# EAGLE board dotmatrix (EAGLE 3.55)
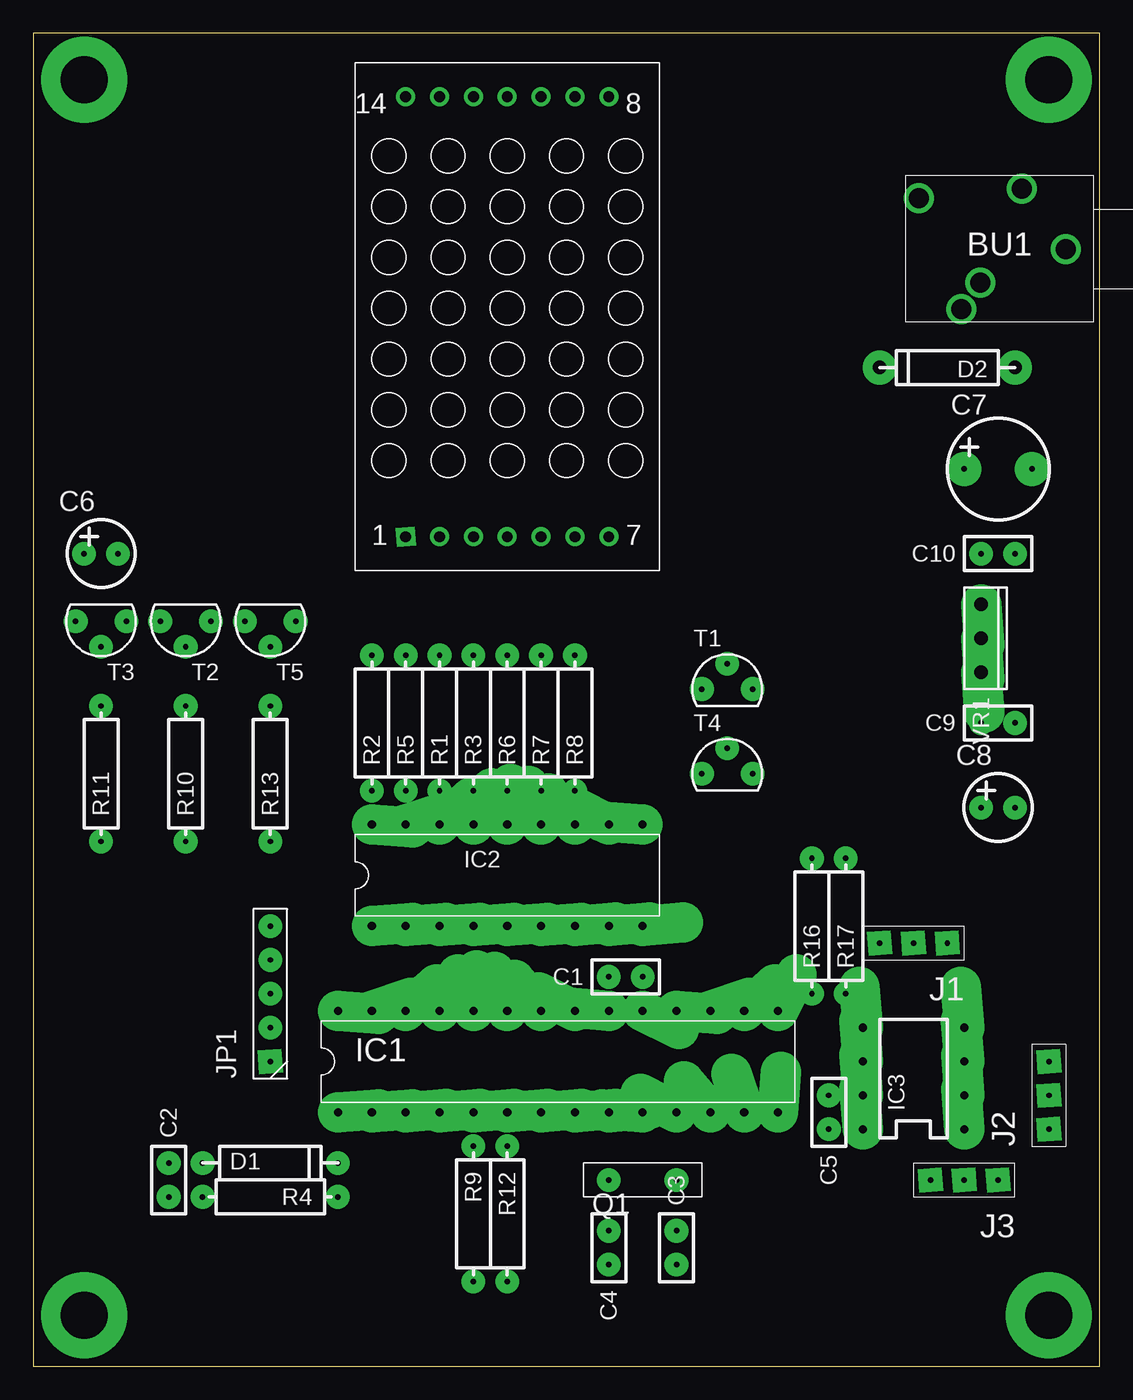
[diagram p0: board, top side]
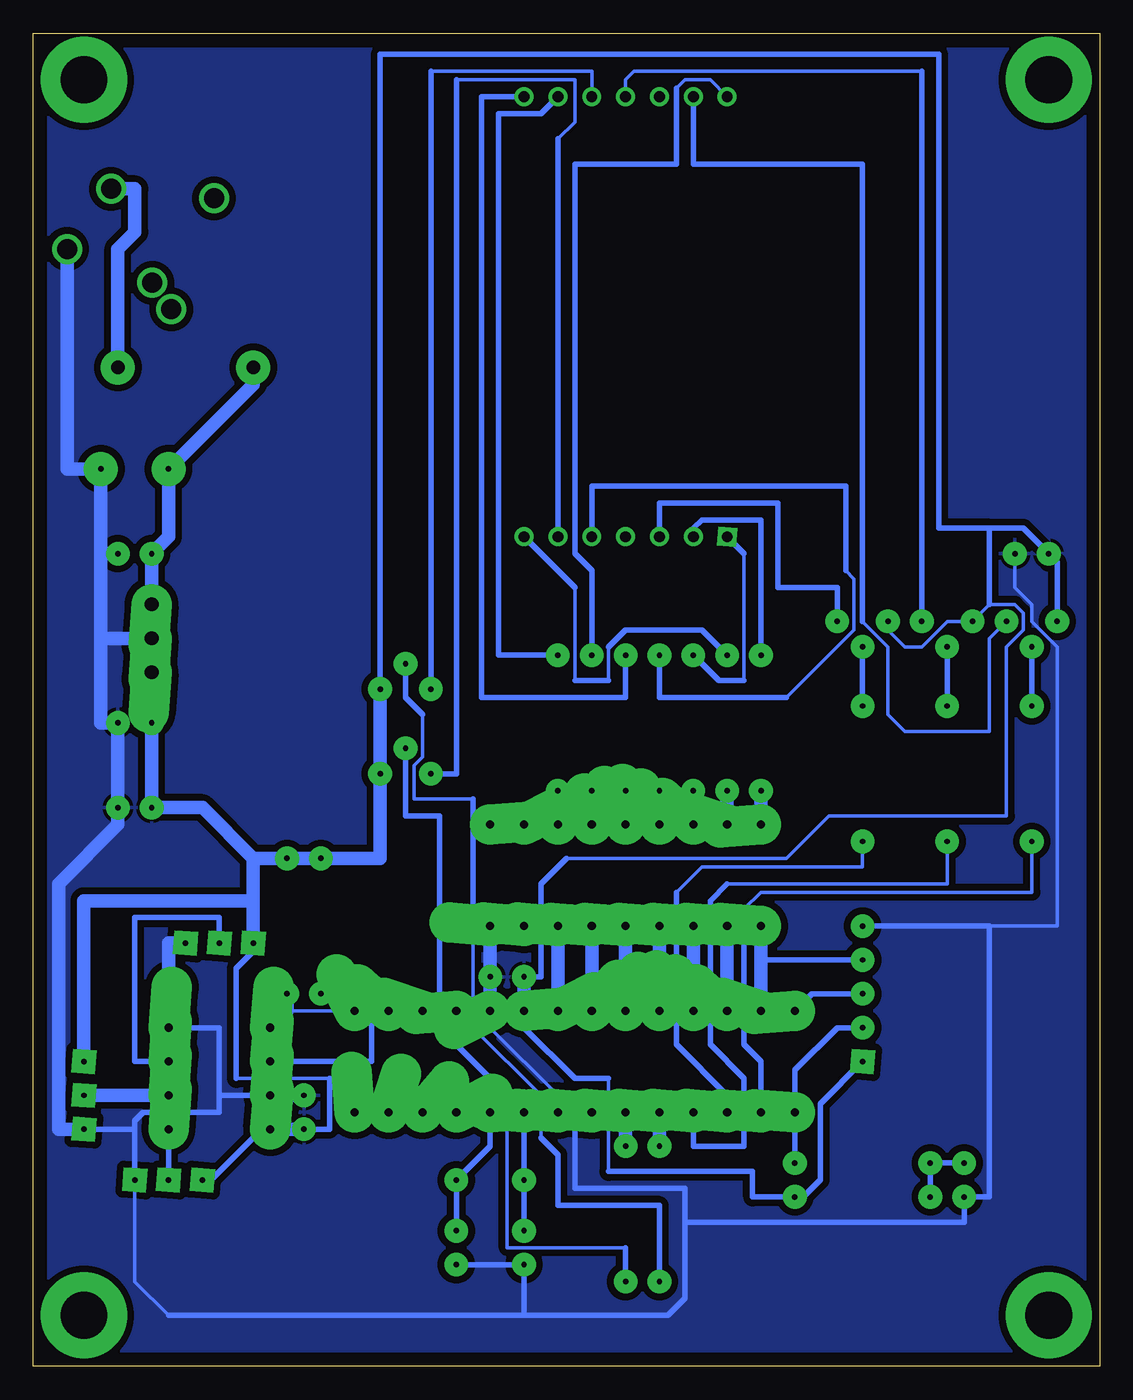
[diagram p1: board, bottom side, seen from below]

Size 80 x 100 mm. Coordinates in mm from the lower left corner, seen from the top.
Outline: 0,0 80,0 80,100 0,100 0,0
Copper layers used: Bottom

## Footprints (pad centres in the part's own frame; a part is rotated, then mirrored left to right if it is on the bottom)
_3,5MM = drill 1.499 pad 2.184 round:  0,0;  3.302,-4.521;  7.823,4.521;  6.401,2.54;  11.024,-3.81
RM2,5 = drill 0.406 pad 1.778 round:  -1.27,0;  1.27,0
KO01 = drill 0.406 pad 1.778 round:  -1.27,0;  1.27,0
KO02 = drill 0.406 pad 2.54 round:  -2.54,0;  2.54,0
O04 = drill 0.406 pad 1.778 round:  -5.08,0;  5.08,0
O_1A = drill 1.016 pad 2.54 round:  -5.08,0;  5.08,0
TA1211 = drill 0.813 pad 1.422 square:  0,0 | drill 0.813 pad 1.422 round:  2.54,0;  5.08,0;  7.62,0;  10.16,0;  12.7,0;  15.24,0;  15.24,33.02;  12.7,33.02;  10.16,33.02;  7.62,33.02;  5.08,33.02;  2.54,33.02;  0,33.02
L-28SB = drill 0.61 pad 3.048 offset:  -16.51,-3.81;  -13.97,-3.81;  -1.27,-3.81;  1.27,-3.81;  -11.43,-3.81;  -8.89,-3.81;  -3.81,-3.81;  -6.35,-3.81;  3.81,-3.81;  6.35,-3.81;  8.89,-3.81;  11.43,-3.81;  13.97,-3.81;  16.51,-3.81;  16.51,3.81;  13.97,3.81;  11.43,3.81;  8.89,3.81;  6.35,3.81;  3.81,3.81;  1.27,3.81;  -1.27,3.81;  -3.81,3.81;  -6.35,3.81;  -8.89,3.81;  -11.43,3.81;  -13.97,3.81;  -16.51,3.81
L-18B = drill 0.61 pad 3.048 offset:  -10.16,-3.81;  -7.62,-3.81;  5.08,-3.81;  7.62,-3.81;  -5.08,-3.81;  -2.54,-3.81;  2.54,-3.81;  0,-3.81;  10.16,-3.81;  10.16,3.81;  7.62,3.81;  5.08,3.81;  2.54,3.81;  0,3.81;  -2.54,3.81;  -5.08,3.81;  -7.62,3.81;  -10.16,3.81
L-8B = drill 0.61 pad 3.048 offset:  -3.81,-3.81;  -1.27,-3.81;  1.27,-3.81;  3.81,-3.81;  3.81,3.81;  1.27,3.81;  -1.27,3.81;  -3.81,3.81
MPER_3 = drill 0.406 pad 1.778 square:  -2.54,0;  0,0;  2.54,0
5 = drill 0.406 pad 1.778 square:  0,0 | drill 0.406 pad 1.778 round:  5.08,0;  10.16,0;  7.62,0;  2.54,0
ARZ_ST = drill 0.406 pad 1.778 round:  -2.54,0;  2.54,0
S04 = drill 0.406 pad 1.778 round:  -5.08,0;  5.08,0
92 = drill 0.406 pad 1.778 round:  -1.905,0;  0,1.905;  1.905,0
HRUNG = drill 3.505 pad 6.452 round:  0,0
220A = drill 1.016 pad 3.048 offset:  -2.54,0;  0,0;  2.54,0

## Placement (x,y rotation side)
BU1  BU_3,5MM  [_3,5MM]  77.47,83.82 180 top
C1  C100NK  [RM2,5]  44.45,29.21 180 top
C2  C100NK  [RM2,5]  10.16,13.97 90 top
C3  22p  [RM2,5]  48.26,8.89 90 top
C4  22p  [RM2,5]  43.18,8.89 270 top
C5  C100NK  [RM2,5]  59.69,19.05 270 top
C6  100u  [KO01]  5.08,60.96 0 top
C7  470u /25V  [KO02]  72.39,67.31 0 top
C8  100u  [KO01]  72.39,41.91 0 top
C9  C100NK  [RM2,5]  72.39,48.26 180 top
C10  C100NK  [RM2,5]  72.39,60.96 180 top
D1  BAT41  [O04]  17.78,15.24 0 top
D2  1N4001  [O_1A]  68.58,74.93 180 top
DIS1  DOTA1211  [TA1211]  27.94,62.23 0 top
IC1  16F873P  [L-28SB]  39.37,22.86 0 top
IC2  ULN2803A  [L-18B]  35.56,36.83 0 top
IC3  24C16  [L-8B]  66.04,21.59 90 top
J1  JUMPER_3  [MPER_3]  66.04,31.75 180 top
J2  JUMPER_3  [MPER_3]  76.2,20.32 90 top
J3  JUMPER_3  [MPER_3]  69.85,13.97 180 top
JP1  PINHD-1X5  [5]  17.78,22.86 90 top
Q1  4MHz  [ARZ_ST]  45.72,13.97 0 top
R1  100  [S04]  30.48,48.26 90 top
R2  100  [S04]  25.4,48.26 90 top
R3  100  [S04]  33.02,48.26 90 top
R4  47k  [S04]  17.78,12.7 180 top
R5  100  [S04]  27.94,48.26 90 top
R6  100  [S04]  35.56,48.26 90 top
R7  100  [S04]  38.1,48.26 90 top
R8  100  [S04]  40.64,48.26 90 top
R9  1k  [S04]  33.02,11.43 270 top
R10  1k  [S04]  11.43,44.45 90 top
R11  1k  [S04]  5.08,44.45 90 top
R12  1k  [S04]  35.56,11.43 270 top
R13  1k  [S04]  17.78,44.45 90 top
R16  3k3  [S04]  58.42,33.02 90 top
R17  3k3  [S04]  60.96,33.02 90 top
T1  BC327  [92]  52.07,50.8 0 top
T2  BC327  [92]  11.43,55.88 180 top
T3  BC327  [92]  5.08,55.88 180 top
T4  BC327  [92]  52.07,44.45 0 top
T5  BC327  [92]  17.78,55.88 180 top
U$15  BOHRUNG  [HRUNG]  76.2,96.52 0 top
U$16  BOHRUNG  [HRUNG]  76.2,3.81 0 top
U$26  BOHRUNG  [HRUNG]  3.81,3.81 0 top
U$27  BOHRUNG  [HRUNG]  3.81,96.52 0 top
VR1  7805  [220A]  71.12,54.61 270 top

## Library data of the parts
BU1 = bts
C1-C10 D1 D2 IC1-IC3 J1-J3 JP1 Q1 R1-R13 R16 R17 T1-T5 VR1 = holg_plt
DIS1 = ic_holg
U$15 U$16 U$26 U$27 = holgnorm

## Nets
+5V: C1. C5. C6. C8. C9. IC1. IC3. J1. J2. J3. JP1. R4. R16. R17. T1. T2. T3. T4. T5. VR1.
GND: BU1. C1. C2. C3. C4. C5. C6. C7. C8. C9. C10. IC1. IC2. IC3. J1. J2. J3. JP1. VR1.
N$1: IC1. R10.
N$2: DIS1. R1.
N$3: IC3. J1.
N$4: IC2. R1.
N$5: IC3. J2.
N$6: DIS1. R2.
N$7: IC2. R2.
N$8: DIS1. R3.
N$9: IC2. R3.
N$10: DIS1. R5.
N$11: IC2. R5.
N$12: DIS1. R6.
N$13: IC2. R6.
N$14: IC2. R7.
N$15: IC2. R8.
N$16: DIS1. R7.
N$17: DIS1. R8.
N$18: IC1. IC2. JP1.
N$19: IC1. IC2.
N$20: IC1. IC2.
N$21: IC1. IC2.
N$22: IC1. IC2.
N$23: IC1. IC2.
N$24: IC1. IC2.
N$25: IC3. J3.
N$26: DIS1. T1.
N$27: DIS1. T2.
N$28: DIS1. T3.
N$29: R9. T1.
N$30: R10. T2.
N$31: R11. T3.
N$32: R12. T4.
N$33: R13. T5.
N$34: IC1. R9.
N$35: D1. IC1. JP1.
N$36: IC1. R11.
N$37: DIS1. T4.
N$38: DIS1. T5.
N$39: IC1. R12.
N$40: IC1. R13.
N$41: C2. D1. R4.
N$42: BU1. D2.
N$43: C7. C10. D2. VR1.
N$44: C3. IC1. Q1.
N$46: C4. IC1. Q1.
N$47: IC1. IC3. R17.
N$49: IC1. JP1.
N$50: IC1. IC3. R16.

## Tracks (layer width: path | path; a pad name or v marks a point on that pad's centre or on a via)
+5V
  Bottom 0.254: 64.77,21.59 57.78,21.59 | 3.81,60.33 3.17,60.33 | T5. 15.88,55.24 14.61,53.98 13.34,53.98 11.43,55.88 T2. 8.26,57.15 6.35,57.15 5.71,56.52 5.71,55.24 6.99,53.98 6.99,41.27 20.32,41.27 23.5,38.1 40.01,38.1 | 22.23,12.7 22.86,12.7 | 36.83,14.61 36.83,21.59
  Bottom 0.406: C5. 57.78,17.78 57.78,21.59 | 64.77,21.59 64.77,29.84 63.5,31.11 J1. | 3.17,60.33 T3. | 3.81,60.33 3.81,60.96 5.71,62.87 8.26,62.87 | 8.26,57.15 8.26,62.87 | 22.23,12.7 20.95,13.97 20.95,19.68 17.78,22.86 | 36.83,21.59 39.37,21.59 43.18,25.4 43.18,26.67 | 36.83,14.61 26.04,14.61 26.04,12.7 22.86,12.7 | 40.01,38.1 41.91,36.2 41.91,29.21 C1. | 8.26,62.87 12.06,62.87 12.06,98.42 53.98,98.42 T1. | IC3. 62.87,17.78 66.67,13.97 J3.
  Bottom 1.016: C5. IC3. | T1. T4. 53.98,38.1 R16. R17. 63.5,38.1 | 63.5,38.1 63.5,34.92 | 63.5,34.92 J1. | 63.5,34.92 76.2,34.92 J2. | 43.18,26.67 C1. | VR1. C9. 71.12,41.91 67.31,41.91 63.5,38.1
GND
  Bottom 0.254: 8.26,33.02 3.17,33.02 3.17,53.98 5.08,55.88 5.08,57.15 6.35,58.42 C6. | 45.72,26.67 45.72,25.4 40.64,20.32 40.64,19.05 | 69.85,3.81 72.39,6.35 72.39,13.97
  Bottom 0.406: 72.39,13.97 72.39,17.78 | 72.39,17.78 76.2,17.78 | 48.26,7.62 C4. 43.18,3.81 | 66.04,20.32 66.04,25.4 69.85,25.4 | 66.04,20.32 66.04,19.05 71.75,19.05 72.39,18.41 72.39,17.78 | 66.04,20.32 62.23,20.32 | 17.78,33.02 8.26,33.02 8.26,12.7 10.16,12.7 10.16,10.79 31.11,10.79 | 31.11,10.79 31.11,13.34 39.37,13.34 39.37,17.78 40.64,19.05 | 43.18,3.81 32.38,3.81 31.11,5.08 31.11,10.79 | 43.18,3.81 69.85,3.81
  Bottom 1.016: 62.23,20.32 59.69,20.32 | 69.85,25.4 69.85,31.75 68.58,31.75 | 45.72,26.67 45.72,29.21 45.72,33.02 | 77.47,83.82 77.47,67.31 C7. 74.93,60.96 | 74.93,60.96 73.66,60.96 | 74.93,54.61 74.93,60.96 | 74.93,54.61 71.12,54.61 | 74.93,54.61 74.93,48.26 73.66,48.26 C8. 73.66,40.64 78.11,36.2 78.11,17.78 76.2,17.78
  pour Bottom (isolate 0.508): 79.38,99.06 79.38,0.64 0.64,0.64 0.64,99.06
N$1
  Bottom 0.254: 27.94,36.2 11.43,36.2 11.43,39.37
  Bottom 0.406: 27.94,36.2 29.21,34.92 29.21,24.13 26.67,21.59 26.67,16.51 30.48,16.51 30.48,19.05
N$2
  Bottom 0.254: 26.67,51.44 26.67,60.96
  Bottom 0.406: 26.67,51.44 28.57,51.44 R1. | 26.67,60.96 27.94,62.23
N$3
  Bottom 0.406: 69.85,22.86 72.39,22.86 72.39,33.66 66.04,33.66 66.04,31.75
N$4
  Bottom 1.016: 30.48,40.64 30.48,43.18
N$5
  Bottom 1.016: 69.85,20.32 76.2,20.32
N$6
  Bottom 0.406: R2. 25.4,63.5 29.84,63.5 30.48,62.87 30.48,62.23
N$7
  Bottom 1.016: IC2. 25.4,43.18
N$8
  Bottom 0.254: 23.5,50.16 18.41,55.24 18.41,59.05 19.05,59.69
  Bottom 0.406: 23.5,50.16 33.02,50.16 R3. | 19.05,59.69 19.05,66.04 38.1,66.04 38.1,62.23
N$9
  Bottom 1.016: 33.02,40.64 33.02,43.18
N$10
  Bottom 0.254: 36.83,53.98 36.83,51.44 | 39.37,51.44 39.37,58.42
  Bottom 0.406: 36.83,53.98 35.56,55.24 29.84,55.24 R5. | 36.83,51.44 39.37,51.44 | 39.37,58.42 43.18,62.23
N$11
  Bottom 1.016: 27.94,40.64 27.94,43.18
N$12
  Bottom 0.406: R6. 35.56,50.16 46.35,50.16 46.35,95.25 43.18,95.25
N$13
  Bottom 1.016: 35.56,40.64 35.56,43.18
N$14
  Bottom 1.016: 38.1,40.64 38.1,43.18
N$15
  Bottom 1.016: 40.64,40.64 40.64,43.18
N$16
  Bottom 0.254: 31.75,95.89 31.11,96.52 29.21,96.52 DIS1.
  Bottom 0.406: 31.75,95.89 31.75,90.17 39.37,90.17 39.37,60.96 38.1,59.69 R7.
N$17
  Bottom 0.406: R8. 45.09,53.34 45.09,93.98 41.91,93.98 40.64,95.25
N$18
  Bottom 0.406: 17.78,30.48 25.4,30.48
  Bottom 1.016: 25.4,33.02 25.4,30.48 25.4,26.67
N$19
  Bottom 1.016: 27.94,26.67 27.94,33.02
N$20
  Bottom 1.016: 30.48,26.67 30.48,33.02
N$21
  Bottom 1.016: 33.02,26.67 33.02,33.02
N$22
  Bottom 1.016: 35.56,26.67 35.56,33.02
N$23
  Bottom 1.016: 38.1,26.67 38.1,33.02
N$24
  Bottom 1.016: 40.64,26.67 40.64,33.02
N$25
  Bottom 0.406: 69.85,13.97 69.85,17.78
N$26
  Bottom 0.254: 50.16,97.16 38.1,97.16 38.1,95.25
  Bottom 0.406: 50.16,50.8 50.16,97.16
N$27
  Bottom 0.254: 13.34,97.16 34.92,97.16 35.56,96.52 35.56,95.25
  Bottom 0.406: 13.34,55.88 13.34,97.16
N$28
  Bottom 0.254: 17.78,55.88 15.88,53.98 15.88,48.9 14.61,47.62 8.26,47.62 8.26,54.61 6.99,55.88
  Bottom 0.406: 17.78,55.88 17.78,90.17 30.48,90.17 30.48,95.25
N$29
  Bottom 0.254: 41.91,17.14 41.91,20.32 46.99,25.4 46.99,32.38 | 46.99,42.55 51.44,42.55 51.44,45.09 50.8,45.72 50.8,48.9
  Bottom 0.406: 41.91,17.14 40.64,15.88 40.64,12.06 33.02,12.06 R9. | 46.99,32.38 46.99,42.55 | 50.8,48.9 52.07,50.16 52.07,52.7
N$30
  Bottom 0.406: R10. 11.43,53.98
N$31
  Bottom 0.406: R11. 5.08,53.98
N$32
  Bottom 0.254: 35.56,8.89 44.45,8.89 44.45,20.32
  Bottom 0.406: 44.45,20.32 49.53,25.4 49.53,41.27 52.07,41.27 52.07,46.35 | R12. 35.56,8.89
N$33
  Bottom 0.406: R13. 17.78,53.98
N$34
  Bottom 1.016: 33.02,16.51 33.02,19.05
N$35
  Bottom 0.406: D1. 22.86,19.05 22.86,22.23 19.68,25.4 JP1.
N$36
  Bottom 0.254: 26.67,34.29 25.4,35.56 5.08,35.56 5.08,39.37
  Bottom 0.406: 26.67,34.29 26.67,24.13 25.4,22.86 25.4,19.05
N$37
  Bottom 0.254: 40.64,92.08 39.37,93.34 39.37,96.52 48.26,96.52
  Bottom 0.406: 48.26,96.52 48.26,44.45 50.16,44.45 | 40.64,92.08 40.64,62.23
N$38
  Bottom 0.406: 19.68,55.88 19.68,58.42 24.13,58.42 24.13,64.77 33.02,64.77 33.02,62.23
N$39
  Bottom 1.016: 35.56,16.51 35.56,19.05
N$40
  Bottom 0.254: 31.75,35.56 29.84,37.47 17.78,37.47 17.78,39.37
  Bottom 0.406: 31.75,35.56 31.75,24.13 27.94,20.32 27.94,19.05
N$41
  Bottom 0.406: R4. 12.7,15.24 C2.
N$42
  Bottom 1.016: 74.17,88.34 72.39,88.34 72.39,85.09 73.66,83.82 73.66,74.93
N$43
  Bottom 1.016: D2. 63.5,73.66 69.85,67.31 69.85,62.23 C10. 71.12,57.15
N$44
  Bottom 0.406: C3. Q1. 45.72,16.51 45.72,19.05
N$46
  Bottom 0.406: 43.18,19.05 43.18,13.97 43.18,10.16
N$47
  Bottom 0.254: 55.88,26.67 60.96,26.67
  Bottom 1.016: 62.23,25.4 60.96,26.67 60.96,27.94
N$49
  Bottom 0.406: IC1. 21.59,27.94 17.78,27.94
N$50
  Bottom 0.406: 55.88,22.86 54.61,22.86 54.61,29.21 57.15,29.21 58.42,27.94 | 55.88,22.86 62.23,22.86 | 55.88,19.05 55.88,22.86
